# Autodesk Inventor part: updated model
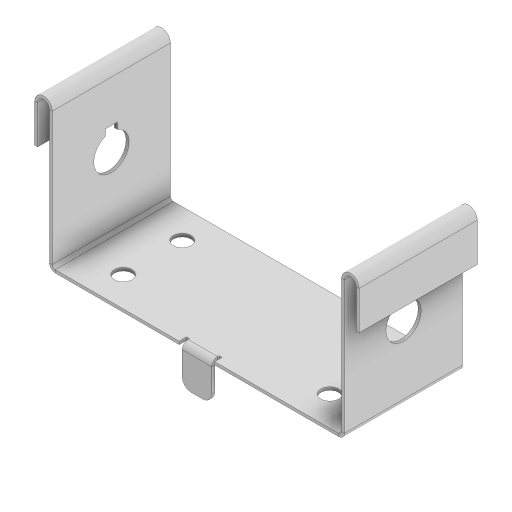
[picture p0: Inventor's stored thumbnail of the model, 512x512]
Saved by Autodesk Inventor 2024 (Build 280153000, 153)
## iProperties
Created: 2021-06
Part Number: updated model
Material: Generic
Document SubType Name: Sheet Metal
Designer: ASUS Laptop
Density: 1 g/cm^3
Flat Pattern Width: 5.12619 cm
Flat Pattern Length: 23.1855 cm
Flat Pattern Area: 118.853 cm^2
Sheet Metal Rule: Default_mm
Sheet Metal Width: 51.262 mm
Sheet Metal Length: 231.855 mm
Sheet Metal Area: 11885.332 mm^2
Appearance: Default
Author: ASUS Laptop
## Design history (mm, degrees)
node "Face1"
sketch "Sketch3"
  geometry: L1 (0, 0)-(0, 40) reference; L2 (100, 0)-(0, 0) reference; 1 further point
  dimensions: "d3" = 15 distance from line of L1 point (15, 10); "d4" = 10 distance from line of L2 point (15, 10)
hole "Hole1" sketch "Sketch3" diameter "d5" = 6; stored, may be unused: countersink angle "d9" = 90 deg, drill point angle "d11" = 118 deg; dims "d6" = 6, "d7" = 6, "d8" = 2, "d10" = 1 (= Thickness)
pattern_linear "Rectangular Pattern1" dims "d14" = 20, "d17" = 70
node "Flange1"
feature "Hem1" dims "d2" = 1 (= Thickness), "d28" = 1 (= BendReliefWidth), "d29" = 0.5 (= BendReliefDepth), "d30" = 2 (= MinimumRemnant), "d31" = 1 (= TransitionRadius), "d32" = 16, "d33" = 4, "d34" = 2 (= 0.5 x d33), "SeamGap" = 0.01
feature "Hem2" dims "d2" = 1 (= Thickness), "d35" = 1 (= BendReliefWidth), "d36" = 0.5 (= BendReliefDepth), "d37" = 2 (= MinimumRemnant), "d38" = 1 (= TransitionRadius), "d39" = 16, "d40" = 4, "d41" = 2 (= 0.5 x d40), "SeamGap" = 0.01
feature "iFeature15:1"
feature "iFeature15:2"
node "Flange2"
feature "Corner Round1" dims "d69" = 3
body "Solid1"
sketch "Sketch2"
  geometry: L1 (0, 0)-(-100, 0); L2 (-100, 0)-(-100, -40); L3 (-100, -40)-(0, -40); L4 (0, -40)-(0, 0)
  constraints: 8 end point, 2 parallel, 1 horizontal, 1 perpendicular
  dimensions: "d0" = 40 distance of L3.end L1.start; "d1" = 100 distance of L2.end L3.end
face "Plate1" dims "d2" = 1 (= Thickness)
sketch "Sketch4"
  geometry: L1 through (0, -20) direction (-5.44e-32, 1); L2 through (-25, 0) direction (-1, -9.38e-32); L3 (-50, 0)-(-50, -40); L4 (-50, -40)-(0, -40)
  constraints: 6 end point, 1 horizontal, 1 perpendicular, 1 vertical
face "Plate2" dims "d2" = 1 (= Thickness), "d18" = 1 (= BendReliefWidth), "d19" = 0.5 (= BendReliefDepth), "d20" = 2 (= MinimumRemnant), "d21" = 1 (= TransitionRadius), "d22" = 50, "d23" = 90 deg, "d24" = 1 (= BendRadius), "d25" = 4 (= CornerReliefSize), "d26" = 1 (= GapSize), "d27" = 1 (= JacobiRadiusSize), "SeamGap" = 0.01
bend "Bend1" dims "d2" = 1 (= Thickness), "d18" = 1 (= BendReliefWidth), "d19" = 0.5 (= BendReliefDepth), "d20" = 2 (= MinimumRemnant), "d21" = 1 (= TransitionRadius), "d22" = 50, "d23" = 90 deg, "d24" = 1 (= BendRadius), "SeamGap" = 0.01
feature "Corner1" dims "d22" = 50, "d23" = 90 deg, "d25" = 4 (= CornerReliefSize), "d26" = 1 (= GapSize), "d27" = 1 (= JacobiRadiusSize)
sketch "Sketch7"
  geometry: L1 (0, 0)-(40, 0) reference; L2 (40, 0)-(40, -48) reference; 2 further points
  dimensions: "d42" = 25 distance from line of point (20, -25) L1; "d43" = 20 distance from line of L2 point (20, -25)
sketch "Sketch8"
  geometry: L1 (40, 0)-(0, 0) reference; L2 (40, -48)-(40, 0) reference; 2 further points
  dimensions: "d50" = 25 distance from line of point (20, -25) L1; "d51" = 20 distance from line of point (20, -25) L2
sketch "Sketch9"
  geometry: L1 (-53, 0)-(-43, 0); L2 (-43, 0)-(-43, 13); L3 (-43, 13)-(-53, 13); L4 (-53, 13)-(-53, 0)
  constraints: 8 end point
face "Plate3" dims "d2" = 1 (= Thickness), "d58" = 1 (= BendReliefWidth), "d59" = 0.5 (= BendReliefDepth), "d60" = 2 (= MinimumRemnant), "d61" = 1 (= TransitionRadius), "d62" = 10, "d63" = 13, "d64" = 90 deg, "d65" = 1 (= BendRadius), "d66" = 4 (= CornerReliefSize), "d67" = 1 (= GapSize), "d68" = 1 (= JacobiRadiusSize), "SeamGap" = 0.01
bend "Bend2" dims "d2" = 1 (= Thickness), "d58" = 1 (= BendReliefWidth), "d59" = 0.5 (= BendReliefDepth), "d60" = 2 (= MinimumRemnant), "d61" = 1 (= TransitionRadius), "d63" = 13, "d64" = 90 deg, "d65" = 1 (= BendRadius), "SeamGap" = 0.01
feature "Corner2" dims "d63" = 13, "d64" = 90 deg, "d66" = 4 (= CornerReliefSize), "d67" = 1 (= GapSize), "d68" = 1 (= JacobiRadiusSize)
sketch "Sketch5"
  geometry: L1 (1, 0)-(0, 0); L2 (-4, 0)-(-4, -13); L3 (-4, -13)-(-5, -13); L4 (-5, -13)-(-5, 0); A1 r 2 centre (-2, 0) between (0, 0) and (-4, 0); A2 r 3 centre (-2, 0) between (1, 0) and (-5, 0)
  constraints: 8 end point, 4 point on circle
sketch "Sketch6"
  geometry: L1 (1, 0)-(0, 0); L2 (-4, 0)-(-4, -13); L3 (-4, -13)-(-5, -13); L4 (-5, -13)-(-5, 0); A1 r 2 centre (-2, 0) between (0, 0) and (-4, 0); A2 r 3 centre (-2, 0) between (1, 0) and (-5, 0)
  constraints: 8 end point, 4 point on circle
feature "Definition1"
other parameters: "Thickness" = 1 (derived), "BendRadius" = 1 (= Thickness), "BendReliefWidth" = 1 (= Thickness), "BendReliefDepth" = 0.5 (= 0.5 x Thickness), "CornerReliefSize" = 4 (= 4 x Thickness), "MinimumRemnant" = 2 (= 2 x Thickness), "TransitionRadius" = 1 (= BendRadius), "JacobiRadiusSize" = 1 (= BendRadius), "GapSize" = 1 (= Thickness), "d49" = 0, "d57" = 0, "BendRadius" = 1, "BendReliefDepth" = 0.5, "BendReliefWidth" = 1, "CornerReliefSize" = 4, "GapSize" = 1, "JacobiRadiusSize" = 1, "MinimumRemnant" = 2, "Thickness" = 1, "TransitionRadius" = 1
